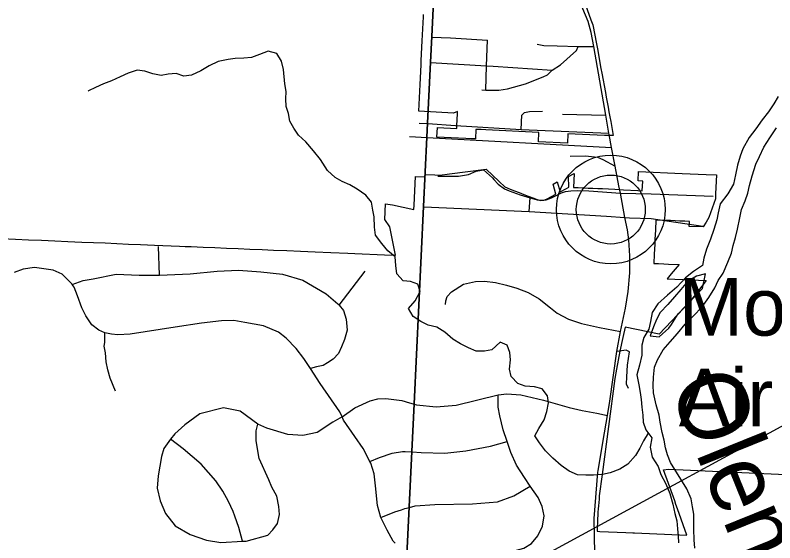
# Model space of a CAD drawing. Extents: x 0 to 34, y 0 to 22.
# Drawn here: x 17.338 to 18.377, y 7.594 to 8.316 of the extents above; entities that cross this region are included whole.
import ezdxf

# ---------------------------------------------------------------- set-up
doc = ezdxf.new("R2010")
doc.units = 0
for name, color, linetype in [('GM_X_City_Street', 7, 'Continuous'), ('GM_X_Corporation', 7, 'Continuous'), ('GM_X_Major_River', 7, 'Continuous'), ('GM_X_Major_River_Text', 7, 'Continuous'), ('GM_X_Minor_River', 7, 'Continuous'), ('GM_X_State_Route', 7, 'Continuous'), ('GM_X_Township_Road', 7, 'Continuous'), ('GM_X_Unincorporated', 7, 'Continuous'), ('GM_X_Unincorporated_Location', 7, 'Continuous'), ('GM_X_Unincorporated_Text', 7, 'Continuous'), ('SH_Text', 7, 'Continuous')]:
    doc.layers.add(name, color=color, linetype=linetype)

msp = doc.modelspace()

# ---------------------------------------------------------------- linework, layer by layer
at = {"layer": 'GM_X_City_Street'}
for points in [[(17.8773, 8.1496), (17.9014, 8.1484), (18.1539, 8.1347)], [(18.0972, 8.1229), (18.118, 8.1233), (18.1345, 8.1213), (18.1419, 8.1184), (18.1586, 8.1091)]]:
    msp.add_lwpolyline(points, dxfattribs=at)
at = {"layer": 'GM_X_Corporation'}
for points in [[(17.8446, 6.9681), (17.8671, 7.4375), (17.8707, 7.5101), (17.8738, 7.5765), (17.877, 7.6426), (17.8806, 7.7185), (17.8837, 7.7838), (17.8967, 8.054), (17.9012, 8.149), (17.9021, 8.168), (17.9061, 8.2515), (17.9078, 8.2866), (17.9129, 8.3931), (17.9061, 8.3935), (16.8906, 8.4459), (16.6112, 8.4601), (16.5003, 8.4668), (16.2652, 8.4813), (16.0546, 8.4904), (15.3473, 8.5302)], [(19.1791, 8.3374), (18.0903, 8.3893), (18.0835, 8.3895), (17.9129, 8.3931), (17.9078, 8.2866), (17.9061, 8.2515), (17.9021, 8.168), (17.9012, 8.149), (17.8967, 8.054), (17.8837, 7.7838), (17.8806, 7.7185), (17.877, 7.6426), (17.8738, 7.5765), (17.8707, 7.5101), (17.8671, 7.4375), (17.8446, 6.9681)], [(18.1158, 8.3365), (18.1256, 8.3096), (18.1283, 8.3026), (18.1332, 8.2767), (18.1344, 8.2699), (18.1393, 8.243), (18.1405, 8.2365), (18.1455, 8.2099), (18.1465, 8.2035), (18.1478, 8.1967), (18.1493, 8.1899), (18.1496, 8.1866), (18.1502, 8.1835), (18.1515, 8.1767), (18.1527, 8.1702), (18.1559, 8.1513), (18.1442, 8.1513), (18.0939, 8.1536), (18.0933, 8.1406), (18.0538, 8.1425), (18.0544, 8.1555), (17.9816, 8.1589), (17.9752, 8.1592), (17.9683, 8.1595), (17.9676, 8.1465), (17.9612, 8.1468), (17.9544, 8.1471), (17.9148, 8.149), (17.9155, 8.162), (17.942, 8.1608), (17.9423, 8.1677), (17.9424, 8.17), (17.9431, 8.1842), (17.9376, 8.1818), (17.89, 8.1843), (17.8918, 8.2212), (17.8931, 8.2477), (17.8935, 8.254), (17.8948, 8.2807), (17.8964, 8.3137), (17.8966, 8.317)], [(17.3194, 8.01), (17.3384, 8.0092), (17.3561, 8.0084), (17.3739, 8.0077), (17.3919, 8.0069), (17.4098, 8.0061), (17.429, 8.0053), (17.4451, 8.0047), (17.4609, 8.004), (17.477, 8.0033), (17.493, 8.0026), (17.5093, 8.0019), (17.5285, 8.0011), (17.5399, 8.0006), (17.5626, 7.9997), (17.5703, 7.9994), (17.5787, 7.999), (17.5949, 7.9984), (17.6109, 7.9977), (17.6271, 7.997), (17.643, 7.9964), (17.6591, 7.9957), (17.6759, 7.995), (17.6913, 7.9943), (17.7097, 7.9935), (17.7282, 7.9927), (17.7482, 7.9919), (17.7695, 7.991), (17.7931, 7.99), (17.8025, 7.9895), (17.843, 7.9878), (17.858, 7.9872), (17.8503, 8.026), (17.8435, 8.036), (17.8445, 8.0575), (17.8542, 8.0563), (17.8834, 8.0498), (17.8837, 8.056), (17.8857, 8.0951), (17.8989, 8.0945), (17.8993, 8.0979), (17.9122, 8.0972), (17.9187, 8.0968), (17.9322, 8.0985), (17.9821, 8.105), (17.9999, 8.088), (18.0076, 8.0807), (18.0149, 8.0778), (18.0211, 8.0754), (18.0273, 8.073), (18.0336, 8.0706), (18.0397, 8.0682), (18.0459, 8.0658), (18.0519, 8.0634), (18.0565, 8.0624), (18.0613, 8.0627), (18.0658, 8.0644), (18.0716, 8.0676), (18.0776, 8.0709), (18.0737, 8.0846), (18.0796, 8.0876), (18.0833, 8.074), (18.0922, 8.0788), (18.0952, 8.0804), (18.0948, 8.0951), (18.1027, 8.099), (18.1018, 8.0801), (18.1082, 8.0799), (18.1152, 8.0795), (18.1216, 8.0792), (18.1283, 8.0789), (18.1349, 8.0786), (18.1414, 8.0784), (18.1496, 8.078), (18.1583, 8.0776), (18.17, 8.0768), (18.1896, 8.0759), (18.1959, 8.0756), (18.1965, 8.0886), (18.1901, 8.0889), (18.1907, 8.1018), (18.2502, 8.0992), (18.2832, 8.0977), (18.2974, 8.0971), (18.297, 8.0886), (18.2962, 8.0711), (18.2958, 8.0644), (18.287, 8.0388), (18.2831, 8.0325), (18.279, 8.0259), (18.2602, 8.0267), (18.2606, 8.0334), (18.2539, 8.0337), (18.2473, 8.034), (18.2408, 8.0343), (18.2343, 8.0346), (18.2277, 8.0348), (18.2144, 8.0354), (18.2137, 8.0222), (18.2131, 8.009), (18.2128, 8.0023), (18.2122, 7.9889), (18.2117, 7.976), (18.2182, 7.9757), (18.2251, 7.9754), (18.2317, 7.9751), (18.2462, 7.9744), (18.241, 7.9682), (18.2353, 7.9616), (18.2298, 7.9551), (18.2834, 7.9528), (18.2611, 7.9235), (18.2188, 7.8794), (18.1723, 7.8888), (18.1691, 7.8745), (18.1651, 7.8559), (18.1604, 7.8314), (18.1583, 7.8185), (18.1408, 7.6872), (18.1369, 7.6578), (18.1367, 7.6534), (18.1358, 7.6441), (18.1353, 7.6399), (18.135, 7.6355), (18.1348, 7.6311), (18.1347, 7.6267), (18.1342, 7.6095), (18.1378, 7.6092), (18.1496, 7.6087), (18.1733, 7.6078), (18.1828, 7.6073), (18.1852, 7.6072), (18.2568, 7.6038), (18.2439, 7.6399), (18.2419, 7.6458), (18.2402, 7.6511), (18.2249, 7.6936), (18.2318, 7.6942), (18.6231, 7.6767)]]:
    msp.add_lwpolyline(points, dxfattribs=at)
at = {"layer": 'GM_X_Major_River'}
for points in [[(18.3818, 8.2046), (18.3756, 8.1947), (18.3687, 8.1834), (18.3599, 8.1728), (18.3514, 8.1604), (18.3422, 8.1483), (18.3333, 8.1328), (18.3298, 8.123), (18.3263, 8.1105), (18.3235, 8.0972), (18.3208, 8.0847), (18.3127, 8.0711), (18.3023, 8.0575), (18.2996, 8.0454), (18.298, 8.0355), (18.2937, 8.0226), (18.289, 8.0094), (18.2839, 7.9957), (18.28, 7.9832), (18.2784, 7.973), (18.2658, 7.9651), (18.2551, 7.9565), (18.2429, 7.9433), (18.2303, 7.9328), (18.2173, 7.9207), (18.2092, 7.909), (18.2072, 7.8965), (18.2048, 7.8859), (18.1979, 7.8745), (18.1952, 7.8643), (18.195, 7.8503), (18.1922, 7.8366), (18.1883, 7.8233), (18.1909, 7.81), (18.193, 7.7994), (18.1945, 7.7899), (18.1951, 7.7792), (18.1965, 7.7682), (18.1972, 7.7587), (18.2005, 7.7484), (18.2091, 7.7373), (18.2067, 7.7244), (18.2093, 7.7107), (18.2175, 7.6981), (18.2212, 7.6871), (18.2279, 7.6741), (18.2335, 7.6611), (18.2375, 7.6463), (18.2404, 7.6337), (18.243, 7.6238), (18.244, 7.6128), (18.245, 7.6029), (18.2453, 7.5934)], [(18.2676, 7.5864), (18.2666, 7.5974), (18.2664, 7.6122), (18.2665, 7.6225), (18.2662, 7.6328), (18.2647, 7.6427), (18.2626, 7.6537), (18.2566, 7.6674), (18.2488, 7.6808), (18.2402, 7.6941), (18.2346, 7.7037), (18.2305, 7.714), (18.2276, 7.7235), (18.2258, 7.7341), (18.2229, 7.7444), (18.2203, 7.7585), (18.2189, 7.7684), (18.2149, 7.7825), (18.2112, 7.7988), (18.2106, 7.8087), (18.2114, 7.8201), (18.2127, 7.8338), (18.2166, 7.844), (18.2243, 7.8576), (18.2339, 7.8689), (18.2438, 7.8802), (18.2546, 7.893), (18.2656, 7.904), (18.2779, 7.9164), (18.2871, 7.9292), (18.2952, 7.9428), (18.2998, 7.9527), (18.3064, 7.9629), (18.313, 7.9776), (18.318, 7.9901), (18.3204, 8.0004), (18.3235, 8.0113), (18.3259, 8.0231), (18.3291, 8.0386), (18.3318, 8.05), (18.3365, 8.0618), (18.3404, 8.072), (18.3427, 8.0826), (18.3463, 8.0959), (18.3513, 8.1118), (18.356, 8.1224), (18.3622, 8.1352), (18.3703, 8.1481), (18.3795, 8.1617)], [(18.2825, 7.9619), (18.2699, 7.9586), (18.2577, 7.9511), (18.2485, 7.9402), (18.2401, 7.9304), (18.2309, 7.9198), (18.2202, 7.9089), (18.2152, 7.8991), (18.2113, 7.8892), (18.2066, 7.8771), (18.2191, 7.8755), (18.2321, 7.8875)], [(18.2321, 7.8875), (18.2356, 7.8924), (18.2448, 7.9072), (18.2548, 7.9174), (18.267, 7.9298), (18.2781, 7.9418), (18.2825, 7.9619)]]:
    msp.add_lwpolyline(points, dxfattribs=at)
at = {"layer": 'GM_X_Minor_River'}
for points in [[(18.2041, 7.7438), (18.1977, 7.7331), (18.1923, 7.7233), (18.1866, 7.7131), (18.1759, 7.701), (18.1653, 7.6942), (18.152, 7.6894), (18.1414, 7.6872), (18.1289, 7.6861), (18.1187, 7.6862), (18.1074, 7.6866), (18.096, 7.6916), (18.0847, 7.6993), (18.0734, 7.7096), (18.0636, 7.7196), (18.0554, 7.7302), (18.049, 7.7402), (18.0543, 7.75), (18.0616, 7.7617), (18.0651, 7.7735), (18.0674, 7.7852), (18.0663, 7.7947), (18.0588, 7.8042), (18.0482, 7.8073), (18.0358, 7.8078), (18.0256, 7.8117), (18.0165, 7.8212), (18.0143, 7.8311), (18.0155, 7.844), (18.0144, 7.8539), (18.0111, 7.8642), (18.0013, 7.8684), (17.9899, 7.8578), (17.98, 7.856), (17.9687, 7.8561), (17.9581, 7.8603), (17.9471, 7.8661), (17.9366, 7.8722), (17.9257, 7.8818), (17.9147, 7.8887), (17.903, 7.8914), (17.8928, 7.8964), (17.8823, 7.9033), (17.8759, 7.9144), (17.885, 7.925), (17.8919, 7.9374), (17.8886, 7.9477), (17.8787, 7.9512), (17.8685, 7.952), (17.8599, 7.9619), (17.8588, 7.9733), (17.8577, 7.9851), (17.8476, 7.9932), (17.8397, 8.0031), (17.831, 8.0145), (17.8296, 8.0255), (17.8289, 8.0396), (17.8274, 8.0491), (17.8252, 8.0597), (17.8177, 8.0693), (17.8057, 8.0777), (17.7955, 8.0838), (17.7853, 8.0881), (17.7755, 8.0938), (17.7653, 8.1034), (17.7556, 8.1183), (17.7462, 8.1301), (17.7356, 8.1423), (17.7255, 8.1515), (17.7191, 8.1614), (17.7138, 8.1709), (17.712, 8.1812), (17.7087, 8.1907), (17.708, 8.2013), (17.7084, 8.2112), (17.7069, 8.2218), (17.7048, 8.2416), (17.7022, 8.253), (17.6958, 8.2633), (17.6841, 8.2668), (17.672, 8.2619), (17.661, 8.2578), (17.6507, 8.2571), (17.639, 8.2564), (17.6292, 8.2554), (17.6155, 8.2524), (17.6034, 8.2464), (17.592, 8.2397), (17.5791, 8.2337), (17.5685, 8.2322), (17.5579, 8.2361), (17.5473, 8.235), (17.5378, 8.2332), (17.5261, 8.2356), (17.5152, 8.2394), (17.5046, 8.2406), (17.4925, 8.2366), (17.4814, 8.2313), (17.4697, 8.2261), (17.4587, 8.222), (17.4477, 8.2167)], [(17.4477, 8.2167), (17.4382, 8.2122), (17.4378, 8.2119)]]:
    msp.add_lwpolyline(points, dxfattribs=at)
at = {"layer": 'GM_X_State_Route'}
for points in [[(18.1503, 8.1524), (18.1499, 8.1544), (18.146, 8.1789), (18.1295, 8.2728), (18.1257, 8.2924), (18.1218, 8.3072), (18.1072, 8.3422), (18.0905, 8.3888)], [(18.1639, 8.0821), (18.1586, 8.1091), (18.1539, 8.1347), (18.1503, 8.1524)], [(18.1352, 7.6902), (18.1353, 7.6922), (18.1424, 7.7337), (18.1482, 7.768), (18.1515, 7.7875), (18.1609, 7.8555), (18.1662, 7.8828), (18.1729, 7.9146), (18.1767, 7.9376), (18.179, 7.963), (18.179, 7.9863), (18.1775, 8.0085), (18.1754, 8.0219), (18.1719, 8.0387), (18.1659, 8.0721), (18.1639, 8.0821)], [(18.1602, 7.3956), (18.1583, 7.4012), (18.1506, 7.4327), (18.1404, 7.4906), (18.133, 7.5404), (18.1312, 7.5553), (18.1302, 7.6267), (18.1352, 7.6902)]]:
    msp.add_lwpolyline(points, dxfattribs=at)
at = {"layer": 'GM_X_Township_Road'}
for p, q in [((17.908, 8.286), (17.9333, 8.2847)), ((17.9333, 8.2847), (17.984, 8.2819)), ((17.9917, 8.2459), (18.0725, 8.2407)), ((18.0868, 8.1802), (18.146, 8.1789)), ((17.9403, 8.165), (18.0303, 8.1594)), ((18.0303, 8.1594), (18.1499, 8.1544)), ((18.041, 8.0473), (18.0423, 8.066)), ((17.5354, 7.9601), (17.5338, 7.9991)), ((17.781, 7.9187), (17.8169, 7.9655))]:
    msp.add_line(p, q, dxfattribs=at)
for points in [[(17.9762, 8.2138), (17.9816, 8.2133), (17.9861, 8.2132), (17.9994, 8.2131), (18.0115, 8.2152), (18.0362, 8.2217), (18.06, 8.2313), (18.0662, 8.2343), (18.0725, 8.2407), (18.0839, 8.2477), (18.1058, 8.2677), (18.1079, 8.273)], [(17.9816, 8.2133), (17.9827, 8.2465), (17.984, 8.2819)], [(18.0522, 8.2764), (18.0612, 8.2743), (18.0796, 8.2738)], [(18.0796, 8.2738), (18.1079, 8.273), (18.1295, 8.2728)], [(17.9063, 8.2509), (17.9827, 8.2465), (17.9917, 8.2459)], [(18.0303, 8.1594), (18.0309, 8.1791), (18.0349, 8.1826), (18.0414, 8.1842), (18.0592, 8.1847)], [(17.8907, 8.1682), (17.9023, 8.1674), (17.9403, 8.165)], [(17.9163, 8.0953), (17.9445, 8.0955), (17.9582, 8.098), (17.9686, 8.1025), (17.9787, 8.1041)], [(17.9787, 8.1041), (17.9909, 8.093), (17.9927, 8.091)], [(17.9927, 8.091), (17.9987, 8.0845), (18.0071, 8.0782), (18.0139, 8.0753), (18.0286, 8.07), (18.0423, 8.066), (18.0519, 8.0633), (18.0575, 8.0628), (18.0644, 8.0631), (18.0717, 8.0658), (18.0855, 8.0727), (18.091, 8.0745), (18.0979, 8.0756), (18.1076, 8.076), (18.1227, 8.0756), (18.1659, 8.0721), (18.208, 8.0714), (18.2929, 8.068)], [(17.8969, 8.0535), (18.041, 8.0473), (18.147, 8.0406), (18.1719, 8.0387), (18.1784, 8.0385)], [(18.1784, 8.0385), (18.208, 8.0374), (18.2788, 8.0272)], [(17.8579, 7.5932), (17.8552, 7.596), (17.8469, 7.6109), (17.8382, 7.6283), (17.8335, 7.6448), (17.8306, 7.6714), (17.8288, 7.6881), (17.8243, 7.7026), (17.8231, 7.7048), (17.8138, 7.7227), (17.8025, 7.7391), (17.7871, 7.7616), (17.785, 7.7661), (17.7818, 7.7727), (17.7551, 7.8116), (17.7419, 7.832), (17.7329, 7.8459), (17.7224, 7.8596), (17.7088, 7.8737), (17.6982, 7.8818), (17.6778, 7.8906), (17.6521, 7.8953), (17.6369, 7.8977), (17.6203, 7.8974), (17.5926, 7.8941), (17.5569, 7.8886), (17.4951, 7.8791), (17.4781, 7.8784), (17.4697, 7.8792), (17.4603, 7.8812), (17.4523, 7.8846), (17.4425, 7.8919), (17.4343, 7.9041), (17.429, 7.9151), (17.423, 7.9315), (17.4185, 7.9437), (17.4158, 7.9474), (17.4152, 7.9483), (17.402, 7.9613), (17.3899, 7.967), (17.3645, 7.9706), (17.3486, 7.968), (17.3364, 7.9635)], [(17.4158, 7.9474), (17.4307, 7.9527), (17.4447, 7.955), (17.4758, 7.9612), (17.5075, 7.9599), (17.5354, 7.9601), (17.5774, 7.962), (17.614, 7.9655), (17.6432, 7.9666), (17.6739, 7.9647), (17.7036, 7.9615), (17.7312, 7.953), (17.7633, 7.9342), (17.7791, 7.9209), (17.781, 7.9187), (17.7871, 7.9117), (17.7908, 7.8999), (17.7919, 7.8847), (17.7884, 7.8718), (17.7845, 7.8619), (17.7803, 7.8528), (17.7727, 7.8449), (17.7651, 7.84), (17.759, 7.8362), (17.7503, 7.8344), (17.7419, 7.832)], [(17.9265, 7.9197), (17.9269, 7.925), (17.9289, 7.9307), (17.9346, 7.9371), (17.9513, 7.9477), (17.9676, 7.9514), (17.9801, 7.9517), (17.9949, 7.9497), (18.01, 7.9462), (18.0244, 7.9423), (18.0395, 7.9362), (18.0547, 7.9274), (18.0701, 7.9151), (18.0796, 7.9079), (18.0947, 7.8998), (18.1125, 7.8936), (18.1374, 7.8882), (18.1662, 7.8828)], [(17.475, 7.8013), (17.4679, 7.8188), (17.4646, 7.8302), (17.4624, 7.8413), (17.4613, 7.8534), (17.4598, 7.8626), (17.4606, 7.8679), (17.4603, 7.8812)], [(18.177, 7.8046), (18.1743, 7.8105), (18.1749, 7.8209), (18.1756, 7.8366), (18.1784, 7.8548), (18.1736, 7.8575), (18.1609, 7.8555)], [(17.8791, 7.7846), (17.8839, 7.7833), (17.8868, 7.7825), (17.9137, 7.7799), (17.9414, 7.7821), (17.9986, 7.7963), (18.0104, 7.7977), (18.0298, 7.796), (18.0608, 7.7887), (18.0956, 7.7786), (18.1138, 7.7747), (18.1338, 7.7712), (18.1482, 7.768)], [(17.8917, 7.5549), (17.9001, 7.5631), (17.9108, 7.5703), (17.9241, 7.5763), (17.9442, 7.5777), (17.9802, 7.5783), (18.0154, 7.5811), (18.0336, 7.586), (18.0443, 7.5927), (18.053, 7.6029), (18.0592, 7.6162), (18.0615, 7.6306), (18.0589, 7.6432), (18.0533, 7.6557), (18.0426, 7.6711), (18.0345, 7.6828), (18.0236, 7.7), (18.0161, 7.7171), (18.0109, 7.7323), (18.0056, 7.7483), (18.0008, 7.7673), (17.9986, 7.7791), (17.9986, 7.7963)], [(17.785, 7.7661), (17.8027, 7.7783), (17.8236, 7.788), (17.8338, 7.7906), (17.8448, 7.791), (17.8668, 7.7882), (17.8772, 7.7852), (17.8791, 7.7846)], [(17.785, 7.7661), (17.7723, 7.7587), (17.751, 7.7447), (17.7316, 7.7403), (17.7108, 7.7419), (17.6821, 7.7504), (17.6697, 7.756), (17.6458, 7.7738), (17.6227, 7.7781), (17.5905, 7.7699), (17.5699, 7.7552), (17.5562, 7.7427), (17.5505, 7.7356), (17.5413, 7.7227), (17.5379, 7.7117), (17.5336, 7.6851), (17.532, 7.6684), (17.5364, 7.6509), (17.5435, 7.6338), (17.5567, 7.6166), (17.5771, 7.6047), (17.5994, 7.597), (17.6191, 7.5939), (17.6487, 7.5956), (17.654, 7.596), (17.6836, 7.6038), (17.6904, 7.6113), (17.6966, 7.62), (17.6996, 7.6322), (17.6986, 7.6432), (17.696, 7.6573), (17.6892, 7.6698), (17.6851, 7.6797), (17.6716, 7.7091), (17.6676, 7.733), (17.6676, 7.7467), (17.6697, 7.756)], [(17.6487, 7.5956), (17.6439, 7.6146), (17.6383, 7.6302), (17.636, 7.6363), (17.6296, 7.65), (17.6218, 7.6641), (17.6123, 7.6782), (17.5924, 7.7011), (17.5679, 7.7222), (17.5505, 7.7356)], [(17.8715, 7.7185), (17.8808, 7.718), (17.8933, 7.7174), (17.9255, 7.7161), (17.9543, 7.7193), (17.9881, 7.726), (18.0109, 7.7323)], [(17.8231, 7.7048), (17.8365, 7.7105), (17.8535, 7.7161), (17.8676, 7.7187), (17.8715, 7.7185)], [(17.8664, 7.6389), (17.871, 7.6404), (17.8772, 7.642), (17.885, 7.6441), (17.9119, 7.6459), (17.9634, 7.6467), (17.9979, 7.6496), (18.0203, 7.6578), (18.0426, 7.6711)], [(17.8382, 7.6283), (17.8573, 7.6359), (17.8664, 7.6389)]]:
    msp.add_lwpolyline(points, dxfattribs=at)
at = {"layer": 'GM_X_Unincorporated'}
for radius in [0.0744, 0.0472]:
    msp.add_circle((18.1528, 8.0498), radius, dxfattribs=at)
at = {"layer": 'GM_X_Unincorporated_Location'}
msp.add_line((18.1528, 8.0498), (18.1528, 8.0498), dxfattribs=at)
at = {"layer": 'SH_Text'}
msp.add_lwpolyline([(20.0151, 8.6388), (15.974, 6.4414), (20.0151, 8.1004)], close=True, dxfattribs=at)

# ---------------------------------------------------------------- texts
at = {"layer": 'GM_X_Major_River_Text'}
msp.add_text('Olentangy', height=0.09469, rotation=292.0058, dxfattribs=at).set_placement((18.2315, 7.8083))
at = {"layer": 'GM_X_Unincorporated_Text'}
for s, p in [('Mount', (18.2458, 7.8772)), ('Air', (18.2458, 7.753))]:
    msp.add_text(s, height=0.07898, rotation=0, dxfattribs=at).set_placement(p)

doc.saveas('drawing.dxf')
